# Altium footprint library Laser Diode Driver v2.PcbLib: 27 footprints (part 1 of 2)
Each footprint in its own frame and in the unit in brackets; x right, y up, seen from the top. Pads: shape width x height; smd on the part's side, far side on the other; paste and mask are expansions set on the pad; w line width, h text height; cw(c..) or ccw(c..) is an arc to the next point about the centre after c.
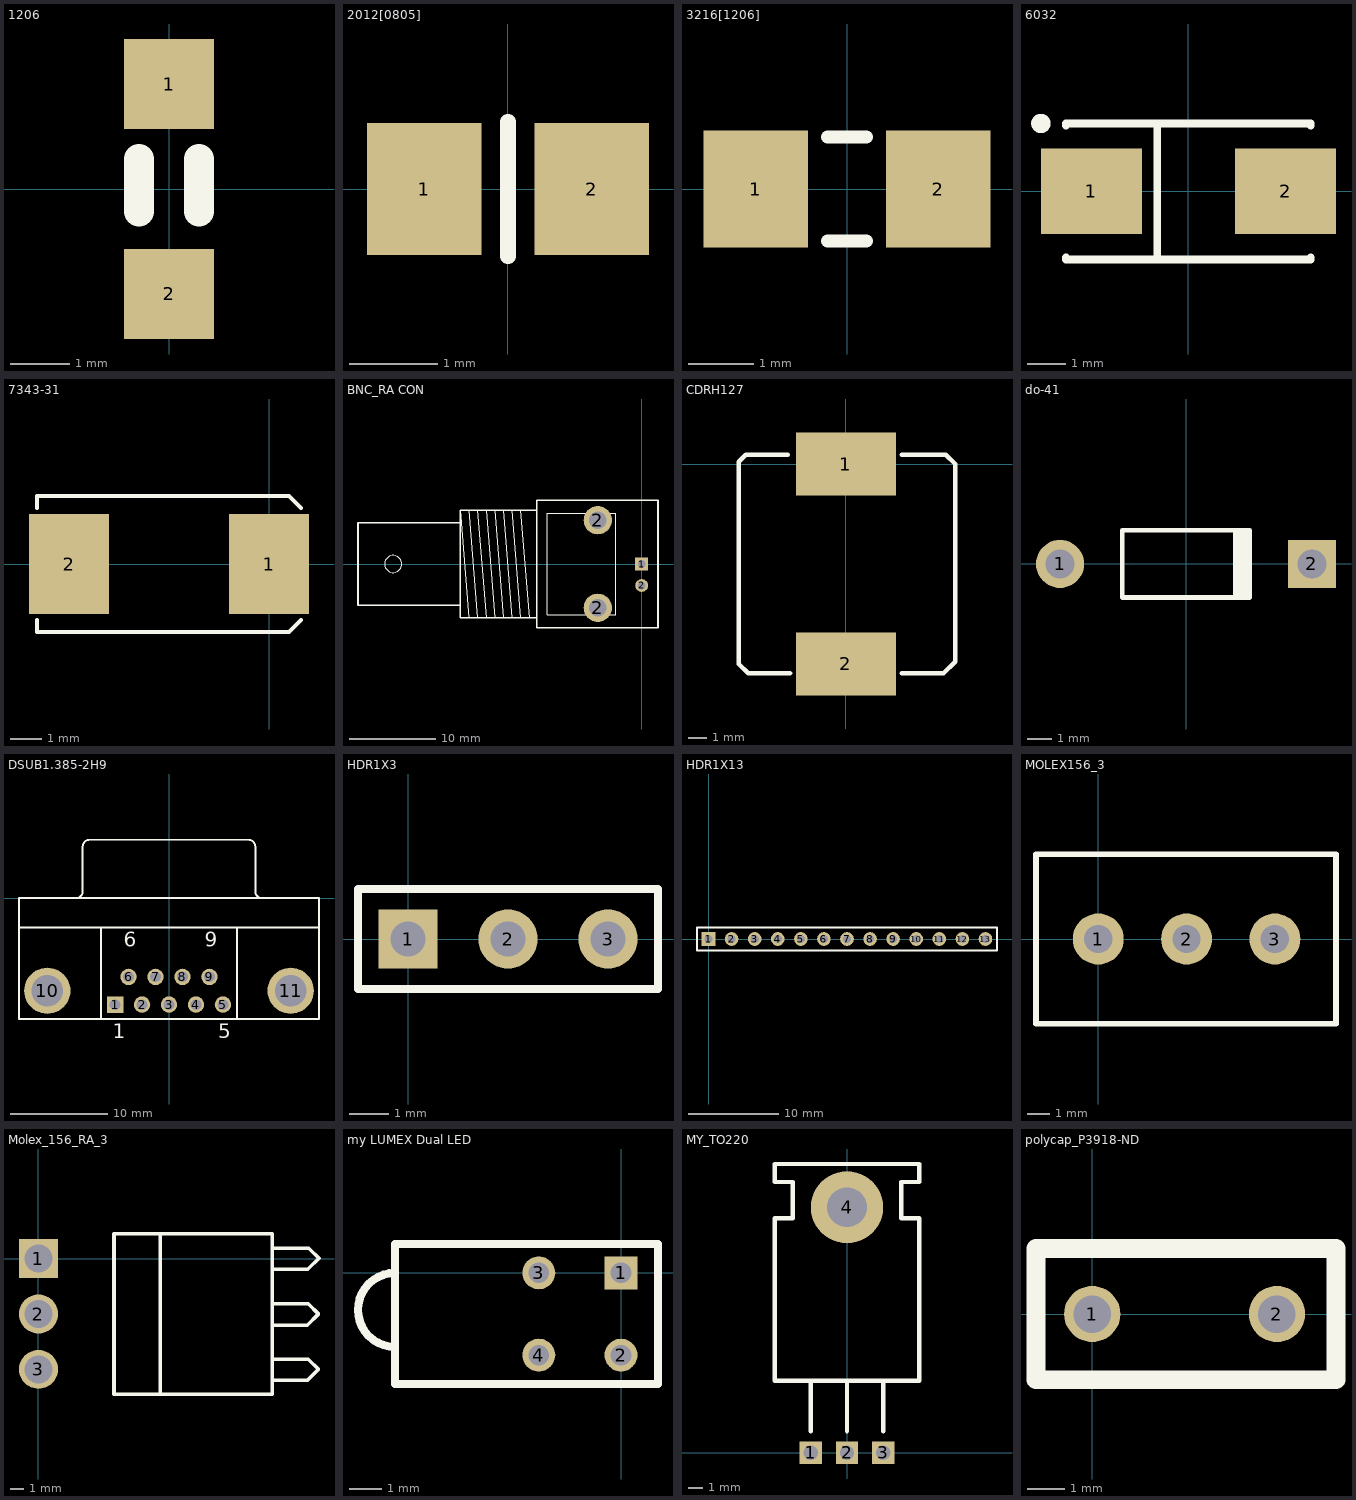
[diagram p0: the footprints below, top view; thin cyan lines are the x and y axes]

## 1206 [mil]
pads (2):
  rect 60x60 smd: 1(0,70) 2(0,-70)
Top Overlay:
  lines w20: -20,-15 -20,20 ; 20,-15 20,20

## 2012[0805] [mm] "Chip Resistor; Body 2.0 x 1.3 mm (LxW typ)"
height 2.54
pads (2):
  rect 1.3x1.5 smd: 1(-0.95,0) 2(0.95,0)
Top Overlay:
  lines w0.178: 0,-0.762 0,0.762

## 3216[1206] [mm] "Chip Resistor; Body 3.2 x 1.6 mm (LxW typ)"
height 2.54
pads (2):
  rect 1.6x1.8 smd: 1(-1.4,0) 2(1.4,0)
Top Overlay:
  lines w0.2: -0.3,-0.8 0.3,-0.8 ; -0.3,0.8 0.3,0.8
3D body: height 0.48, standoff 0, extent -2.286,-1.016 2.286,1.016

## 6032 [mm] "Capacitor, SM Tantalum; Body 6.0 x 3.2 mm (LxW typ)"
height 2.8
pads (2):
  rect 2.6x2.2 smd: 1(-2.5,0) 2(2.5,0)
Top Overlay:
  circle w0.25: c-3.8,1.75 r0.125
  lines w0.2: -3.15,-1.7 -3.15,-1.75 3.15,-1.75 3.15,-1.7 ; -3.15,1.7 -3.15,1.75 3.15,1.75 3.15,1.7 ; -0.8,-1.75 -0.8,1.75

## 7343-31 [mm]
height 9.65
pads (2):
  rect 2.54x3.175 smd: 1(0,0) 2(-6.35,0)
Top Overlay:
  lines w0.127: -7.366,-1.778 -7.366,-2.159 0.635,-2.159 1.016,-1.778 ; -7.366,1.778 -7.366,2.159 0.635,2.159 1.016,1.778

## BNC_RA CON [mm] "Connector; BNC Elbow"
height 9.65
pads (4):
  rect 1.5x1.5 hole 0.9: 1(0,0)
  round 3.3 hole 2: 2(-5.1,-5.1) 2(-5.1,5.1)
  round 1.5 hole 0.9: 2(0,-2.5)
Top Overlay:
  circle w0.025: c-28.9,0 r1
  lines w0.025: -20.1,-6.25 -21.1,6.25 ; -20.1,6.25 -19.1,-6.25 ; -19.1,6.25 -18.1,-6.25 ; -18.1,6.25 -17.1,-6.25 ; -17.1,6.25 -16.1,-6.25 ; -16.1,6.25 -15.1,-6.25 ; -15.1,6.25 -14.1,-6.25 ; -14.1,6.25 -13.1,-6.25 ; -21.1,-4.8 -33,-4.8 -33,4.8 -21.1,4.8 ; -21.1,-4.8 -21.1,4.8 ; -21.1,-4.8 -21.1,-6.25 -12.2,-6.25 ; -21.1,4.8 -21.1,6.25 ; -21.1,6.25 -12.2,6.25 ; -12.2,-6.25 -12.2,6.25 ; -12.2,-6.25 -12.2,-7.4 1.9,-7.4 1.9,7.4 -12.2,7.4 -12.2,6.25 ; -11,-5.9 -3,-5.9 -3,5.9 -11,5.9 -11,-5.9
  lines w0.2: -21.1,-4.8 -21.1,4.8 ; -21.1,-4.8 -33,-4.8 -33,4.8 -21.1,4.8 ; -21.1,-4.8 -21.1,-6.25 -12.2,-6.25 ; -21.1,4.8 -21.1,6.25 -12.2,6.25 ; -12.2,-6.25 -12.2,6.25 ; -12.2,-6.25 -12.2,-7.4 1.9,-7.4 1.9,7.4 -12.2,7.4 -12.2,6.25

## CDRH127 [mil] "CDRH127 series power inductor footprint."
height 379.92
pads (2):
  rect 215x135 smd: 1(0,0) 2(0,-430)
Top Overlay:
  lines w10: -125,20 -215,20 -230,5 -230,-430 -210,-450 -120,-450 ; 120,-450 210,-450 235,-425 235,0 215,20 120,20

## do-41 [mm] "Diode, Axial; Body 5.2 x 2.7 mm (LxDia. max), Lead Dia. 0.86 mm (max)"
height 2.8
pads (2):
  round 2 hole 1.2: 1(-5.23,0)
  rect 2x2 hole 1.2: 2(5.23,0)
Top Overlay:
  rectangle: 1.95,-1.405 2.75,1.395
  lines w0.2: 2.65,-1.4 -2.65,-1.4 -2.65,1.4 2.65,1.4

## DSUB1.385-2H9 [mm] "Connector; D Subminiature; 9 Position; Right Angle; Pitch 1.385 mm"
height 12.75
pads (11):
  rect 1.69x1.69 hole 1.09: 1(-5.54,-10.92)
  round 1.69 hole 1.09: 2(-2.77,-10.92) 3(0,-10.92) 4(2.77,-10.92) 5(5.54,-10.92) 6(-4.155,-8.08) 7(-1.385,-8.08) 8(1.385,-8.08) 9(4.155,-8.08)
  round 4.76 hole 3.26: 10(-12.495,-9.5) 11(12.495,-9.5)
Top Overlay:
  lines w0.2: -15.4,-3 15.4,-3 ; -9.56,0.005 ccw(c-9.56,0.7) -8.865,0.7 -8.865,5.3 ; -8.86,5.305 cw(c-8.165,5.305) -8.165,6 8.165,6 cw(c8.165,5.305) 8.86,5.305 ; -7,-12.4 -7,-3 ; 7,-12.4 7,-3 ; 8.865,5.3 8.865,0.7 ccw(c9.56,0.7) 9.56,0.005 ; -15.4,-12.4 -15.4,0 15.4,0 15.4,-12.4 -15.4,-12.4
  text "1" at -5.79,-14.375 h1.5
  text "5" at 5.04,-14.375 h1.5
  text "9" at 3.655,-4.975 h1.5
  text "6" at -4.655,-4.975 h1.5

## HDR1X3 [mm] "Connector; Header; 3 Position"
height 9.65
pads (3):
  rect 1.5x1.5 hole 0.9: 1(0,0)
  round 1.5 hole 0.9: 2(2.54,0) 3(5.08,0)
Top Overlay:
  lines w0.2: -1.27,-1.27 -1.27,1.27 6.35,1.27 6.35,-1.27 -1.27,-1.27

## HDR1X13 [mm] "Connector; Header; 13 Position"
height 9.65
pads (13):
  rect 1.5x1.5 hole 0.9: 1(0,0)
  round 1.5 hole 0.9: 2(2.54,0) 3(5.08,0) 4(7.62,0) 5(10.16,0) 6(12.7,0) 7(15.24,0) 8(17.78,0) 9(20.32,0) 10(22.86,0) 11(25.4,0) 12(27.94,0) 13(30.48,0)
Top Overlay:
  lines w0.2: -1.27,-1.27 -1.27,1.27 0.635,1.27 31.75,1.27 31.75,-1.27 -1.27,-1.27

## MOLEX156_3 [mil]
height 379.92
pads (3):
  round 90 hole 50: 1(0,0) 2(156,0) 3(312,0)
Top Overlay:
  lines w10: -110,-150 420,-150 420,150 -110,150 -110,0 -110,-150

## Molex_156_RA_3 [mil] "3 Pin Molex, 0.156mil Spacing, Right Angle"
height 394
pads (3):
  rect 110x110 hole 79: 1(0,0)
  round 110 hole 79: 2(0,-156) 3(0,-312)
Top Overlay:
  lines w10: 343,-382 343,70 ; 659,-343.5 758.5,-343.5 790,-312 761.5,-283.5 659,-283.5 ; 659,-187.5 758.5,-187.5 790,-156 761.5,-127.5 659,-127.5 ; 659,-30 760,-30 791.5,1.5 763,30 659,30 ; 213,-382 659,-382 659,70 213,70 213,-382

## my LUMEX Dual LED [mil] "Stacked Dual LED PCB Rt Angle"
height 379.92
pads (4):
  rect 40x40 hole 25: 1(0,0)
  round 40 hole 25: 2(0,-100) 3(-100,0) 4(-100,-100)
Top Overlay:
  lines w10: -275,-90 cw(c-275,-45) -275,0 ; -275,-135 -275,35 45,35 45,-135 -275,-135

## MY_TO220 [mil]
height 379.92
pads (4):
  rect 62x62 hole 40: 1(-100,0) 2(0,0) 3(100,0)
  round 200 hole 110: 4(0,680)
Top Overlay:
  lines w12: -100,60 -100,200 ; 0,60 0,200 ; 100,60 100,200 ; -200,200 200,200 200,650 150,650 150,750 200,750 200,800 -200,800 -200,750 -150,750 -150,650 -200,650 -200,200

## polycap_P3918-ND [mil]
height 379.92
pads (2):
  round 60 hole 40: 1(0,0) 2(197,0)
Top Overlay:
  lines w20: -60,-70 -60,70 260,70 260,-70 -60,-70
